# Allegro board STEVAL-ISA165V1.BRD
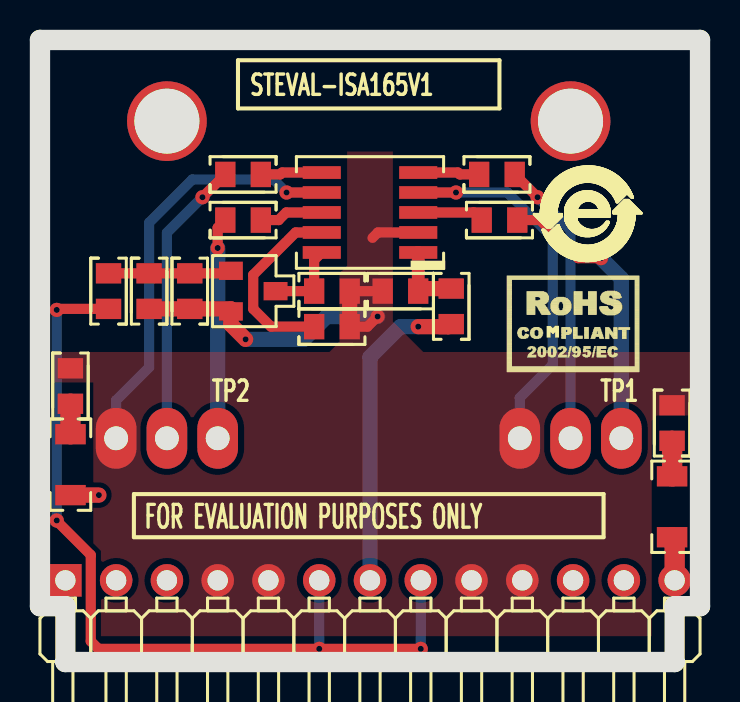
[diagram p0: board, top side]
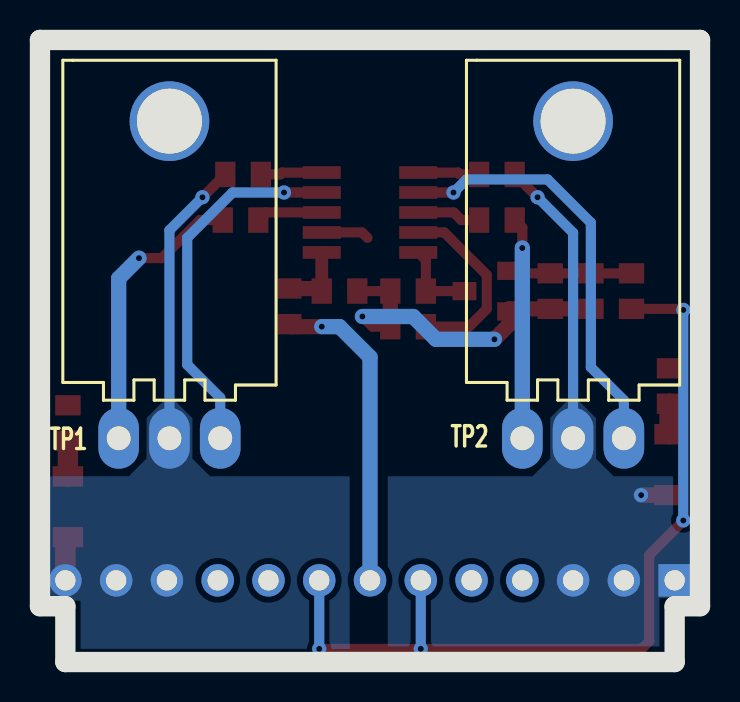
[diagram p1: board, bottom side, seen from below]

Outline 33.02 x 31.14 mm; copper layers: TOP, BOTTOM. Coordinates in mm from the lower left corner of the outline.
Outline path: 0,31.14 33.02,31.14 33.02,2.79 31.75,2.79 31.75,0 1.27,0 1.27,2.79 0,2.79 0,31.14

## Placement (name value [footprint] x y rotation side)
C501  1uF  [CAPC-0805]  18.03 18.57 0 top
C502  2n7  [CAPC-0805]  7.49 18.57 270 top
C503  2N2  [CAPC-0805]  31.62 11.96 90 top
C504  2N2  [CAPC-0805]  1.52 13.82 90 top
JP501  HEADER 13  [STRIP254P-M-13-90]  16.51 4.09 270 top
NOREF  -  []  -31.57 -45.64 0 top
NOREF#2  -  []  -12.45 23.01 90 top
NOREF#3  -  []  1.27 0 0 top
NOREF#4  -  []  -75.79 -157.18 0 top
NOREF#5  -  []  28.42 -103.56 0 top
NOREF#6  -  []  -110.55 -216.11 0 top
NOREF#7  -  []  0 31.14 0 top
NOREF#8  -  []  1.27 0 90 top
NOREF#9  -  []  33.02 2.79 90 top
NOREF#10  -  []  -80.04 -98.95 0 top
Q501  STF60N55F3  [TO220-3PIN-ASSIALE-SLIM]  26.54 27.08 180 bottom
Q502  STF60N55F3  [TO220-3PIN-ASSIALE-SLIM]  6.35 27.08 180 bottom
Q503  BC847C  [SOT23]  10.67 18.57 270 top
R501  0R  [RESC-0805]  20.57 17.81 270 top
R502  100k  [RESC-0805]  14.6 18.57 0 top
R503  0R  [RESC-0805]  14.6 16.79 180 top
R504  0R  [RESC-0805]  22.86 24.41 180 top
R505  0R  [RESC-0805]  10.16 24.41 180 top
R506  0R  [RESC-0805]  22.99 22.12 180 top
R507  0R  [RESC-0805]  10.16 22.12 180 top
R508  1k0  [RESC-0805]  3.43 18.57 270 top
R509  10k  [RESC-0805]  5.46 18.57 90 top
R510  10R  [RESC-1206]  31.62 7.77 270 top
R511  10R  [RESC-1206]  1.52 9.88 270 top
U501  SRK2001  [SSOP100P-620X175-10]  16.51 22.5 180 top

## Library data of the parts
C501 = C-NP_0
C502-C504 = C-NP_1
JP501 = HEADER 9_2
Q501 Q502 = MOS-N_3
Q503 = BC847BL-SOT23_0
R501-R509 = RES_0
R510 R511 = RES_1
U501 = SRK2001_0

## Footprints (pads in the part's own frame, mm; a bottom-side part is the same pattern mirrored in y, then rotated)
CAPC-0805
  rect 1.016x1.27 smd: 1(-0.889,0) 2(0.889,0)
RESC-0805
  rect 1.016x1.27 smd: 1(-0.889,0) 2(0.889,0)
RESC-1206
  rect 1.016x1.524 smd: 1(-1.524,0) 2(1.524,0)
SOT23
  rect 0.914x1.194 smd: 1(-1.016,-1.118) 2(1.016,-1.118) 3(0,1.118)
SSOP100P-620X175-10
  rect 1.905x0.635 smd: 1(-2.413,2) 2(-2.413,1) 3(-2.413,0) 4(-2.413,-1) 5(-2.413,-2) 6(2.413,-2) 7(2.413,-1) 8(2.413,0) 9(2.413,1) 10(2.413,2)
STRIP254P-M-13-90
  rect 1.626x1.626 hole 1.016: 1(0,-15.24)
  round 1.626 hole 1.016: 2(0,-12.7) 3(0,-10.16) 4(0,-7.62) 5(0,-5.08) 6(0,-2.54) 7(0,0) 8(0,2.54) 9(0,5.08) 10(0,7.62) 11(0,10.16) 12(0,12.7) 13(0,15.24)
TO220-3PIN-ASSIALE-SLIM
  round 3.988 hole 3.251: (0,0)
  oval 2.032x3.048 hole 1.194: 1(-2.54,-15.875) 2(0,-15.875) 3(2.54,-15.875)

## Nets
+12V_B: JP501.7 R501.2
DR1_B: JP501.11 JP501.12 JP501.13 Q501.2(DRAIN) R504.1 R510.2
DR2_B: JP501.1 JP501.2 JP501.3 Q502.2(DRAIN) R505.2 R511.2
SRC1_B: C501.1 C502.2 C503.2 C504.2 JP501.4 JP501.5 JP501.9 JP501.10 Q501.3(SOURCE) Q502.3(SOURCE) Q503.2(EMITTER) R502.2 R503.1 R509.1 U501.2(GND) U501.4(SVS1) U501.7(SVS2)
N218439: Q502.1(GATE) R507.2
N218471: R507.1 U501.8(GD2)
N218505: Q501.1(GATE) R506.1
N218507: R506.2 U501.3(GD1)
N218531: R505.1 U501.6(DVS2)
N218537: R504.2 U501.5(DVS1)
N218551: C501.2 R501.1 U501.1(VCC)
N218557: R503.2 U501.9(PROG)
N218559: Q503.3(COLLECTOR) R502.1 U501.10(EN)
N11870840: JP501.6 JP501.8 R508.2
N11870844: C502.1 Q503.1(BASE) R508.1 R509.2
N11877647: C504.1 R511.1
N11878297: C503.1 R510.1

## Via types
v1: diameter 0.711, hole 0.305, TOP to BOTTOM, 14 vias

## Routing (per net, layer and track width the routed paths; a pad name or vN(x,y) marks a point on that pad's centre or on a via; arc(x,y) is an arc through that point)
+12V_B: length 15.9
  TOP w0.762: R501.2 20.45,16.79 v1(18.92,16.79)
  BOTTOM w0.762: JP501.7 16.51,15.27 18.03,16.79 v1(18.92,16.79)
DR1_B: length 16.6
  TOP w0.508: R504.1 v1(24.89,23.27)
  TOP w1.016: R510.2 31.75,6.12 31.75,4.09
  BOTTOM w0.508: Q501.2 26.54,21.62 v1(24.89,23.27)
DR2_B: length 15.8
  TOP w0.508: R505.2 v1(8.13,23.27)
  TOP w0.762: R511.2 v1(2.95,8.36)
  BOTTOM w0.508: v1(8.13,23.27) 6.35,21.49 Q502.2
SRC1_B: length 60.1
  TOP w0.508: U501.7 v1(12.34,23.5) ; v1(16.89,17.3) 16.38,16.79 R503.1 ; U501.2 16.91,21.5 16.64,21.23 ; R502.2 C501.1 ; U501.4 v1(20.81,23.5)
  TOP w0.762: v1(10.29,16.15) 9.55,16.89 Q503.2 9.55,17.68 C502.2 R509.1 ; R503.1 R502.2
  BOTTOM w0.508: Q501.3 24,13.23 25.65,14.88 25.65,21.23 23.38,23.5 v1(20.81,23.5) ; v1(12.34,23.5) 11.68,24.16 7.62,24.16 5.46,22 5.46,14.76 3.81,13.11 Q502.3
  BOTTOM w0.762: v1(16.89,17.3) 14.35,17.3 13.21,16.15 v1(10.29,16.15)
N218439: length 11.1
  TOP w0.508: R507.2 8.89,21.74 v1(8.89,20.73)
  BOTTOM w0.762: v1(8.89,20.73) Q502.1
N218471: length 3.2
  TOP w0.508: R507.1 11.94,22.12 12.32,22.5 U501.8
N218505: length 14.4
  TOP w0.508: R506.1 25.02,22.12 26.92,20.22 v1(28.07,20.22)
  BOTTOM w0.762: Q501.1 29.08,19.2 v1(28.07,20.22)
N218507: length 3.3
  TOP w0.508: R506.2 21.72,22.5 U501.3
N218531: length 3.1
  TOP w0.508: U501.6 12.11,24.5 12.01,24.41 R505.1
N218537: length 3.1
  TOP w0.508: U501.5 20.91,24.5 21.01,24.41 R504.2
N218551: length 3.6
  TOP w0.635: U501.1 C501.2
  TOP w0.762: C501.2 19.05,18.69 R501.1
N218557: length 9.4
  TOP w0.508: U501.9 12.79,21.5 10.67,19.38 10.67,17.68 11.56,16.79 R503.2
N218559: length 4
  TOP w0.508: U501.10 13.72,20.12 R502.1 Q503.3
N11870840: length 43.4
  TOP w0.508: v1(0.84,7.09) 0.84,7.06 2.54,5.36 2.54,1.04 2.92,0.66 v1(13.97,0.66) v1(19.05,0.66) ; v1(0.84,17.63) 0.89,17.68 R508.2
  BOTTOM w0.508: v1(0.84,7.09) v1(0.84,17.63) ; v1(13.97,0.66) 13.97,4.09 ; v1(19.05,0.66) JP501.8
N11870844: length 6.2
  TOP w0.508: Q503.1 9.42,19.46 C502.1 R509.2 R508.1
N11877647: length 1.5
  TOP w1.016: R511.1 C504.1
N11878297: length 1.8
  TOP w1.016: R510.1 C503.1

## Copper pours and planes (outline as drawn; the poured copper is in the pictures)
DR1_B on BOTTOM: 17.53,9.3 24.51,9.3 25.4,10.19 25.4,12.22 26.42,13.23 26.67,13.23 27.69,12.22 27.69,10.19 28.58,9.3 32.64,9.3 32.64,3.2 32.51,3.07 30.99,3.07 30.99,0.66 17.53,0.66
DR2_B on BOTTOM: 15.62,9.3 8.38,9.3 7.49,10.19 7.49,12.22 6.48,13.23 6.22,13.23 5.21,12.22 5.21,10.19 4.32,9.3 0.38,9.3 0.38,3.33 0.51,3.2 2.03,3.2 2.03,0.79 15.62,0.79
SRC1_B on TOP: 2.67,1.3 2.67,14 0.64,14 0.64,15.52 14.48,15.52 14.99,16.03 14.99,19.46 15.37,19.84 15.37,25.55 17.65,25.55 17.65,17.04 19.18,15.52 32.64,15.52 32.64,12.34 30.86,12.34 30.61,12.09 30.61,1.3

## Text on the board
BOTTOM: 02 BOTTOM LAYER
Ref Des/Assembly Bottom: 09 PIANO DI MONTAGGIO BOT
Board Geometry/Soldermask Bottom: 06 SOLDER MASK BOTTOM
Package Geometry/Pastemask Bottom: 08 PASTE MASK BOT
Ref Des/Silkscreen Bottom: TP2 | TP1 | 04 SERIGRAFIA BOTTOM
TOP: 01 TOP LAYER
Ref Des/Assembly Top: 08 PIANO DI MONTAGGIO TOP
Board Geometry/Soldermask Top: 05 SOLDER MASK TOP
Package Geometry/Pastemask Top: 07 PASTE MASK TOP
Ref Des/Silkscreen Top: FOR EVALUATION PURPOSES ONLY | TP2 | STEVAL-ISA165V1 | TP1
PAGE_OUTLINE: STEVAL-ISA165V1 | 03 SERIGRAFIA TOP | 1
BODY_CENTER: 03 SERIGRAFIA LC POWERFLAT
FAB_NOTE: FABRICATION DRAWING
User.15: FIGURE | SIZE | 12.0 | 40.0 | 47.0 | 128.0 | DRILL CHART: TOP to BOTTOM | ALL UNITS ARE IN MILS | PLATED | QTY | 14 | 13 | 6 | 2
User.16: PIANO DI MONTAGGIO LATO TOP E BOTTOM
User.18: PIANO DI MONTAGGIO LATO SALDATURE
